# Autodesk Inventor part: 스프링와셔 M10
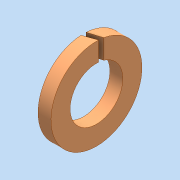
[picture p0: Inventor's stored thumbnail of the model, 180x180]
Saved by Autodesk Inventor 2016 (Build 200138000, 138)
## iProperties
Created: 2024-09
Part Number: 스프링와셔 M10
Material: 일반
Description: 스프링 잠금 와셔
Document SubType Name: Modeling
Designer: pc-7
Density: 1 g/cm^3
Appearance: 기본값
Author: jhkim
Sending System: Autodesk Inventor 2025
Preprocessor: ST-DEVELOPER v20
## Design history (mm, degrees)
node "스프링와셔 M101"
node "솔리드1"
body "Solid1"
